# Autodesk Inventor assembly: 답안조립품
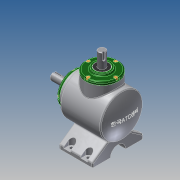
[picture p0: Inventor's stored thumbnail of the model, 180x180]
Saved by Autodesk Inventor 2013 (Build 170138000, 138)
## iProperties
Created: 2017-04
Part Number: 답안조립품
Document SubType Name: Assembly
Designer: Administrator
Author: Administrator
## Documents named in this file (14)
- C:\Users\Administrator\Desktop\470407V1011\답안조립품.iam
- C:\Users\Administrator\Desktop\470407V1011\본체.ipt
- C:\Users\Administrator\Desktop\470407V1011\메인 축.ipt
- 메인 축.ipt
- C:\Users\Administrator\Desktop\470407V1011\키 5x5.ipt
- C:\Users\Administrator\Desktop\470407V1011\베어링 6203.ipt
- C:\Users\Administrator\Desktop\470407V1011\메인 베벨기어.ipt
- C:\Users\Administrator\Desktop\470407V1011\커버.ipt
- C:\Users\Administrator\Desktop\470407V1011\오일실 17 32 8.ipt
- C:\Users\Administrator\Desktop\470407V1011\서브 축.ipt
- 서브 축.ipt
- C:\Users\Administrator\Desktop\470407V1011\키 4x4.ipt
- C:\Users\Administrator\Desktop\470407V1011\서브 베벨기어.ipt
- C:\Users\Administrator\Desktop\470407V1011\볼트 M4.ipt
